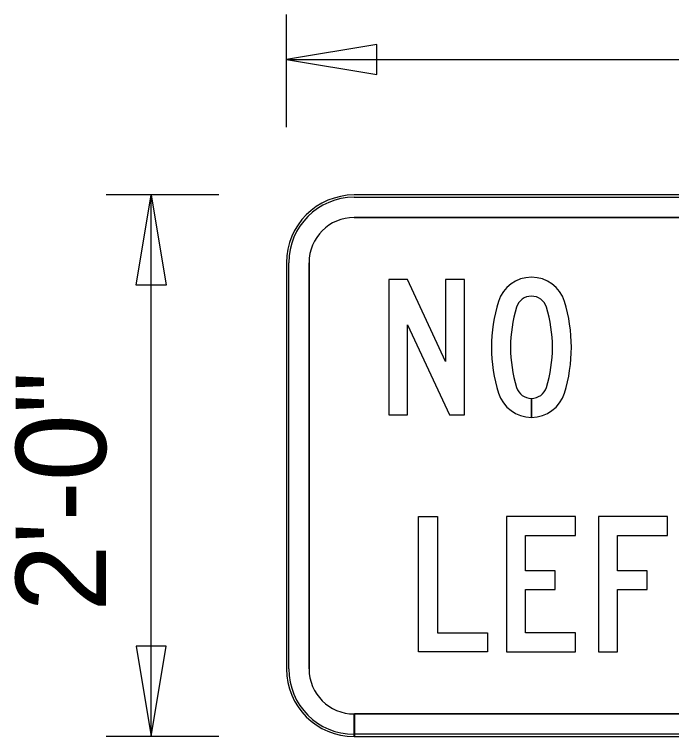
# Model space of a CAD drawing. Extents: x 17890628 to 17890844, y 17897506 to 17897992.
# Drawn here: x 17890811.09 to 17890815.94, y 17897544.34 to 17897549.68 of the extents above; entities that cross this region are included whole.
import ezdxf

# ---------------------------------------------------------------- set-up
doc = ezdxf.new("R2010")
doc.units = 0
for name, color, linetype in [('GSBWFill', 7, 'Continuous'), ('GSColorFill', 7, 'Continuous'), ('GSDims', 7, 'Continuous'), ('GSOutline', 7, 'Continuous')]:
    doc.layers.add(name, color=color, linetype=linetype)

msp = doc.modelspace()

# ---------------------------------------------------------------- linework, layer by layer
at = {"layer": 'GSBWFill'}
for p, q in [((17890820.5961, 17897548.3429), (17890813.5961, 17897548.3429)), ((17890813.5961, 17897548.1762), (17890820.5961, 17897548.1762)), ((17890813.0961, 17897547.8429), (17890813.0961, 17897544.8429)), ((17890813.2628, 17897544.8429), (17890813.2628, 17897547.8429)), ((17890814.9061, 17897546.8404), (17890814.9061, 17897546.7004)), ((17890814.9061, 17897546.7004), (17890814.9061, 17897546.8404)), ((17890813.5961, 17897544.3429), (17890813.5961, 17897544.5096)), ((17890820.5961, 17897544.5096), (17890813.5978, 17897544.5096)), ((17890813.5978, 17897544.5096), (17890813.5978, 17897544.3429)), ((17890813.5978, 17897544.3429), (17890820.5961, 17897544.3429))]:
    msp.add_line(p, q, dxfattribs=at)
for points in [[(17890814.3011, 17897546.7179), (17890814.4111, 17897546.7179), (17890814.4111, 17897547.7179), (17890814.2711, 17897547.7179), (17890814.2711, 17897547.1136), (17890813.9894, 17897547.7179), (17890813.8511, 17897547.7179), (17890813.8511, 17897546.7179), (17890813.9911, 17897546.7179), (17890813.9911, 17897547.3829)], [(17890814.0711, 17897545.9679), (17890814.2111, 17897545.9679), (17890814.2111, 17897545.1079), (17890814.5811, 17897545.1079), (17890814.5811, 17897544.9679), (17890814.0711, 17897544.9679)], [(17890814.8611, 17897545.1079), (17890814.8611, 17897545.4279), (17890815.0802, 17897545.4279), (17890815.0802, 17897545.5679), (17890814.8611, 17897545.5679), (17890814.8611, 17897545.8279), (17890815.2311, 17897545.8279), (17890815.2311, 17897545.9679), (17890814.7211, 17897545.9679), (17890814.7211, 17897544.9679), (17890815.2311, 17897544.9679), (17890815.2311, 17897545.1079)], [(17890815.5411, 17897545.4279), (17890815.7602, 17897545.4279), (17890815.7602, 17897545.5679), (17890815.5411, 17897545.5679), (17890815.5411, 17897545.8279), (17890815.9111, 17897545.8279), (17890815.9111, 17897545.9679), (17890815.4011, 17897545.9679), (17890815.4011, 17897544.9679), (17890815.5411, 17897544.9679)]]:
    msp.add_lwpolyline(points, close=True, dxfattribs=at)
for centre, radius, start, end in [((17890813.5961, 17897547.8429), 0.5, 90, 180), ((17890813.5961, 17897547.8429), 0.3333, 90, 180), ((17890813.5961, 17897544.8429), 0.5, 180, 270), ((17890813.5961, 17897544.8429), 0.3333, 180, 270)]:
    msp.add_arc(centre, radius, start, end, dxfattribs=at)
for centre, major_axis, start_param, end_param in [((17890814.9061, 17897547.4804), (0, 0.255), 5.014824, 7.551546), ((17890814.9061, 17897547.4804), (0, 0.115), 5.014824, 7.551546), ((17890815.7474, 17897547.2179), (0, 1.1363), 1.268361, 1.873232), ((17890814.0648, 17897547.2179), (0, 1.1363), 4.409954, 5.014824), ((17890815.7474, 17897547.2179), (0, 0.9963), 1.268361, 1.873232), ((17890814.0648, 17897547.2179), (0, 0.9963), 4.409954, 5.014824), ((17890814.9061, 17897546.9554), (0, 0.115), 1.873232, 3.141593), ((17890814.9061, 17897546.9554), (0, 0.115), 3.142027, 4.409954), ((17890814.9061, 17897546.9554), (0, 0.255), 1.873232, 3.141593), ((17890814.9061, 17897546.9554), (0, 0.255), 3.141789, 4.409954)]:
    msp.add_ellipse(centre, major_axis=major_axis, ratio=0.999998, start_param=start_param, end_param=end_param, dxfattribs=at)
at = {"layer": 'GSColorFill'}
for p, q in [((17890820.5961, 17897548.3429), (17890813.5961, 17897548.3429)), ((17890820.5961, 17897548.3429), (17890813.5961, 17897548.3429)), ((17890820.5961, 17897548.3429), (17890813.5961, 17897548.3429)), ((17890813.5961, 17897548.3262), (17890820.5961, 17897548.3262)), ((17890813.5961, 17897548.1762), (17890820.5961, 17897548.1762)), ((17890813.0961, 17897547.8429), (17890813.0961, 17897544.8429)), ((17890813.0961, 17897547.8429), (17890813.0961, 17897544.8429)), ((17890813.0961, 17897547.8429), (17890813.0961, 17897544.8429)), ((17890813.1128, 17897544.8429), (17890813.1128, 17897547.8429)), ((17890813.2628, 17897544.8429), (17890813.2628, 17897547.8429)), ((17890814.9061, 17897546.8404), (17890814.9061, 17897546.7004)), ((17890814.9061, 17897546.7004), (17890814.9061, 17897546.8404)), ((17890813.5961, 17897544.3429), (17890813.5961, 17897544.5096)), ((17890820.5961, 17897544.5096), (17890813.5978, 17897544.5096)), ((17890813.5978, 17897544.5096), (17890813.5978, 17897544.3429)), ((17890813.5961, 17897544.3429), (17890813.5961, 17897544.3596)), ((17890813.5961, 17897544.3429), (17890820.5961, 17897544.3429)), ((17890820.5961, 17897544.3596), (17890813.5963, 17897544.3596)), ((17890813.5963, 17897544.3596), (17890813.5963, 17897544.3429)), ((17890813.5963, 17897544.3429), (17890820.5961, 17897544.3429)), ((17890813.5978, 17897544.3429), (17890820.5961, 17897544.3429))]:
    msp.add_line(p, q, dxfattribs=at)
for points in [[(17890814.3011, 17897546.7179), (17890814.4111, 17897546.7179), (17890814.4111, 17897547.7179), (17890814.2711, 17897547.7179), (17890814.2711, 17897547.1136), (17890813.9894, 17897547.7179), (17890813.8511, 17897547.7179), (17890813.8511, 17897546.7179), (17890813.9911, 17897546.7179), (17890813.9911, 17897547.3829)], [(17890814.0711, 17897545.9679), (17890814.2111, 17897545.9679), (17890814.2111, 17897545.1079), (17890814.5811, 17897545.1079), (17890814.5811, 17897544.9679), (17890814.0711, 17897544.9679)], [(17890814.8611, 17897545.1079), (17890814.8611, 17897545.4279), (17890815.0802, 17897545.4279), (17890815.0802, 17897545.5679), (17890814.8611, 17897545.5679), (17890814.8611, 17897545.8279), (17890815.2311, 17897545.8279), (17890815.2311, 17897545.9679), (17890814.7211, 17897545.9679), (17890814.7211, 17897544.9679), (17890815.2311, 17897544.9679), (17890815.2311, 17897545.1079)], [(17890815.5411, 17897545.4279), (17890815.7602, 17897545.4279), (17890815.7602, 17897545.5679), (17890815.5411, 17897545.5679), (17890815.5411, 17897545.8279), (17890815.9111, 17897545.8279), (17890815.9111, 17897545.9679), (17890815.4011, 17897545.9679), (17890815.4011, 17897544.9679), (17890815.5411, 17897544.9679)]]:
    msp.add_lwpolyline(points, close=True, dxfattribs=at)
for centre, radius, start, end in [((17890813.5961, 17897547.8429), 0.5, 90, 180), ((17890813.5961, 17897547.8429), 0.5, 90, 180), ((17890813.5961, 17897547.8429), 0.5, 90, 180), ((17890813.5961, 17897547.8429), 0.4833, 90, 180), ((17890813.5961, 17897547.8429), 0.3333, 90, 180), ((17890813.5961, 17897544.8429), 0.5, 180, 270), ((17890813.5961, 17897544.8429), 0.5, 180, 270), ((17890813.5961, 17897544.8429), 0.5, 180, 270), ((17890813.5961, 17897544.8429), 0.4833, 180, 270), ((17890813.5961, 17897544.8429), 0.3333, 180, 270)]:
    msp.add_arc(centre, radius, start, end, dxfattribs=at)
for centre, major_axis, start_param, end_param in [((17890814.9061, 17897547.4804), (0, 0.255), 5.014824, 7.551546), ((17890814.9061, 17897547.4804), (0, 0.115), 5.014824, 7.551546), ((17890815.7474, 17897547.2179), (0, 1.1363), 1.268361, 1.873232), ((17890814.0648, 17897547.2179), (0, 1.1363), 4.409954, 5.014824), ((17890815.7474, 17897547.2179), (0, 0.9963), 1.268361, 1.873232), ((17890814.0648, 17897547.2179), (0, 0.9963), 4.409954, 5.014824), ((17890814.9061, 17897546.9554), (0, 0.115), 1.873232, 3.141593), ((17890814.9061, 17897546.9554), (0, 0.115), 3.142027, 4.409954), ((17890814.9061, 17897546.9554), (0, 0.255), 1.873232, 3.141593), ((17890814.9061, 17897546.9554), (0, 0.255), 3.141789, 4.409954)]:
    msp.add_ellipse(centre, major_axis=major_axis, ratio=0.999998, start_param=start_param, end_param=end_param, dxfattribs=at)
at = {"layer": 'GSDims'}
for p, q in [((17890813.0961, 17897548.8429), (17890813.0961, 17897549.6762)), ((17890813.0961, 17897549.3429), (17890821.0961, 17897549.3429)), ((17890812.5961, 17897548.3429), (17890811.7628, 17897548.3429)), ((17890812.0961, 17897544.3429), (17890812.0961, 17897548.3429)), ((17890812.5961, 17897544.3429), (17890811.7628, 17897544.3429))]:
    msp.add_line(p, q, dxfattribs=at)
for points in [[(17890813.0961, 17897549.3429), (17890813.7628, 17897549.2318), (17890813.7628, 17897549.454)], [(17890812.0961, 17897548.3429), (17890812.2072, 17897547.6762), (17890811.985, 17897547.6762)], [(17890812.0961, 17897544.3429), (17890812.2072, 17897545.0096), (17890811.985, 17897545.0096)]]:
    msp.add_lwpolyline(points, close=True, dxfattribs=at)
at = {"layer": 'GSOutline'}
for p, q in [((17890820.5961, 17897548.3429), (17890813.5961, 17897548.3429)), ((17890820.5961, 17897548.1762), (17890813.5961, 17897548.1762)), ((17890813.0961, 17897547.8429), (17890813.0961, 17897544.8429)), ((17890813.2628, 17897547.8429), (17890813.2628, 17897544.8429)), ((17890813.5961, 17897544.5096), (17890820.5961, 17897544.5096)), ((17890813.5961, 17897544.3429), (17890820.5961, 17897544.3429))]:
    msp.add_line(p, q, dxfattribs=at)
for points in [[(17890814.3011, 17897546.7179), (17890814.4111, 17897546.7179), (17890814.4111, 17897547.7179), (17890814.2711, 17897547.7179), (17890814.2711, 17897547.1136), (17890813.9894, 17897547.7179), (17890813.8511, 17897547.7179), (17890813.8511, 17897546.7179), (17890813.9911, 17897546.7179), (17890813.9911, 17897547.3829)], [(17890814.0711, 17897545.9679), (17890814.2111, 17897545.9679), (17890814.2111, 17897545.1079), (17890814.5811, 17897545.1079), (17890814.5811, 17897544.9679), (17890814.0711, 17897544.9679)], [(17890814.8611, 17897545.1079), (17890814.8611, 17897545.4279), (17890815.0802, 17897545.4279), (17890815.0802, 17897545.5679), (17890814.8611, 17897545.5679), (17890814.8611, 17897545.8279), (17890815.2311, 17897545.8279), (17890815.2311, 17897545.9679), (17890814.7211, 17897545.9679), (17890814.7211, 17897544.9679), (17890815.2311, 17897544.9679), (17890815.2311, 17897545.1079)], [(17890815.5411, 17897545.4279), (17890815.7602, 17897545.4279), (17890815.7602, 17897545.5679), (17890815.5411, 17897545.5679), (17890815.5411, 17897545.8279), (17890815.9111, 17897545.8279), (17890815.9111, 17897545.9679), (17890815.4011, 17897545.9679), (17890815.4011, 17897544.9679), (17890815.5411, 17897544.9679)]]:
    msp.add_lwpolyline(points, close=True, dxfattribs=at)
for centre, radius, start, end in [((17890813.5961, 17897547.8429), 0.5, 90, 180), ((17890813.5961, 17897547.8429), 0.3333, 90, 180), ((17890813.5961, 17897544.8429), 0.5, 180, 270), ((17890813.5961, 17897544.8429), 0.3333, 180, 270)]:
    msp.add_arc(centre, radius, start, end, dxfattribs=at)
for centre, major_axis, start_param, end_param in [((17890814.9061, 17897547.4804), (0, 0.255), 5.014824, 7.551546), ((17890814.9061, 17897547.4804), (0, 0.115), 5.014824, 7.551546), ((17890815.7474, 17897547.2179), (0, 1.1363), 1.268361, 1.873232), ((17890814.0648, 17897547.2179), (0, 1.1363), 4.409954, 5.014824), ((17890815.7474, 17897547.2179), (0, 0.9963), 1.268361, 1.873232), ((17890814.0648, 17897547.2179), (0, 0.9963), 4.409954, 5.014824), ((17890814.9061, 17897546.9554), (0, 0.115), 1.873232, 4.409954), ((17890814.9061, 17897546.9554), (0, 0.255), 1.873232, 4.409954)]:
    msp.add_ellipse(centre, major_axis=major_axis, ratio=0.999998, start_param=start_param, end_param=end_param, dxfattribs=at)

# ---------------------------------------------------------------- texts
at = {"layer": 'GSDims'}
msp.add_text('2\'-0"', height=0.66667, rotation=90, dxfattribs=at).set_placement((17890811.7628, 17897545.2659))

doc.saveas('drawing.dxf')
